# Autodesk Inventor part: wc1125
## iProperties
Shininess: 64.0
Length Units: 11272
Angle Units: 11279
Time Units: 11290
Mass Units: 11286
Length Display Precision: 3
Angle Display Precision: 2
Compacted: True
Part Number: wc1125
Document SubType Name: Modeling
Created: 2004-08
Designer: John Blackburn
Manufacturer: Standard
Standards Organization: Custom
Material: Delrin, Black
Density: 0.0
Volumn: 0.0
Area: 0.0
PropertySet Name: Model Information
Control State: 0
Master: False
Checked Out: False
Author: John Blackburn
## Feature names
1. Base1
